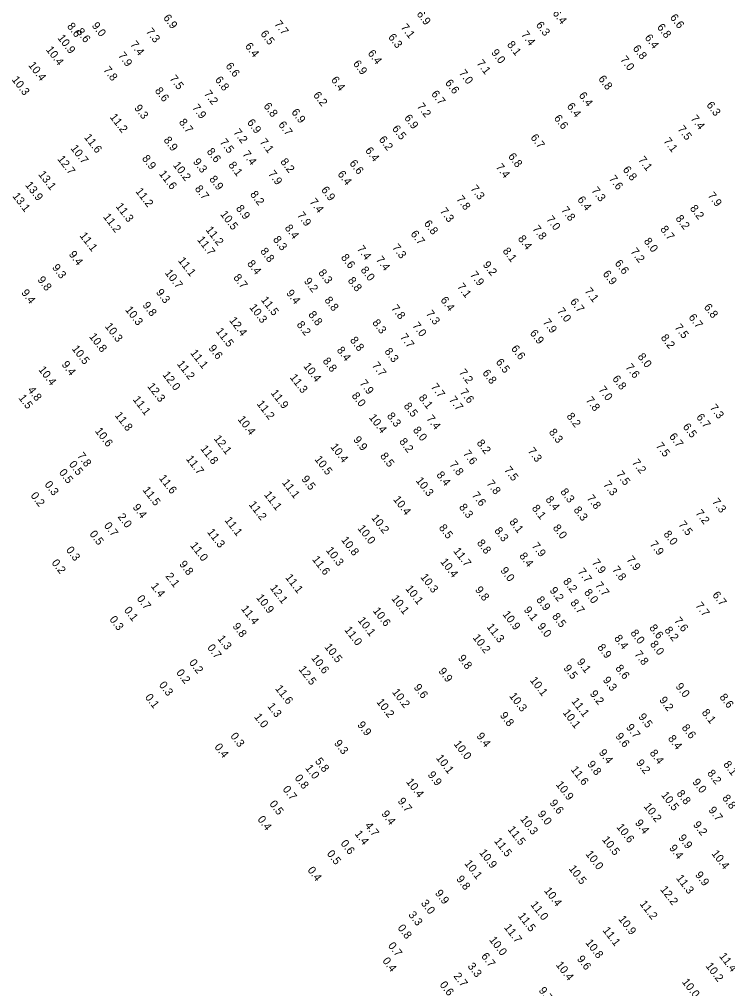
# Model space of a CAD drawing. Extents: x 815385 to 820851, y 582449 to 604245.
# Drawn here: x 818415 to 818858, y 594576 to 595182 of the extents above; entities that cross this region are included whole.
import ezdxf

# ---------------------------------------------------------------- set-up
doc = ezdxf.new("R2010")
doc.units = 0
for name, color, linetype in [('V-TOPO-SOUN-011609', 7, 'Continuous'), ('V-TOPO-SOUN-020509C', 7, 'Continuous'), ('V-TOPO-SOUN-EXCSS', 7, 'Continuous')]:
    doc.layers.add(name, color=color, linetype=linetype)

msp = doc.modelspace()

# ---------------------------------------------------------------- texts
at = {"layer": 'V-TOPO-SOUN-011609'}
for s, p in [('6.9', (818504.66, 595182.61)), ('6.9', (818662.99, 595184.99)), ('6.4', (818747.96, 595185.51)), ('6.6', (818821.32, 595182.82)), ('8.6', (818444.56, 595177.35)), ('7.7', (818574.09, 595178.74)), ('7.1', (818653.09, 595176.68)), ('6.3', (818737.53, 595178.14)), ('6.8', (818813.23, 595176.75)), ('7.3', (818493.86, 595174.04)), ('6.5', (818565.39, 595172.62)), ('6.3', (818645.22, 595170.53)), ('7.4', (818728.28, 595172.12)), ('6.4', (818805.52, 595170.18)), ('7.4', (818483.99, 595165.94)), ('6.4', (818555.75, 595164.88)), ('8.1', (818719.49, 595165.9)), ('6.8', (818798.05, 595163.45)), ('7.9', (818476.46, 595159.02)), ('6.4', (818632.43, 595160.44)), ('9.0', (818709.6, 595160.88)), ('6.6', (818543.62, 595152.52)), ('6.9', (818623.26, 595153.96)), ('7.1', (818700.46, 595154.23)), ('7.0', (818790.22, 595156.52)), ('7.8', (818467.24, 595150.11)), ('7.0', (818689.43, 595148.06)), ('6.8', (818536.98, 595143.9)), ('6.4', (818609.48, 595143.81)), ('6.6', (818680.79, 595141.97)), ('6.8', (818776.52, 595144.48)), ('7.2', (818530.08, 595135.15)), ('6.2', (818598.38, 595134.29)), ('6.7', (818672.1, 595135.07)), ('6.4', (818764.31, 595134.09)), ('7.2', (818663.17, 595127.28)), ('6.4', (818756.88, 595127.34)), ('6.3', (818844.1, 595128.13)), ('7.9', (818522.73, 595126.44)), ('6.9', (818584.74, 595123.65)), ('8.7', (818514.44, 595117.42)), ('6.7', (818576.57, 595115.85)), ('6.9', (818655.24, 595120.06)), ('6.6', (818748.84, 595119.87)), ('7.4', (818834.22, 595119.65)), ('6.5', (818647.68, 595113.35)), ('7.5', (818826.1, 595113.08)), ('8.9', (818504.89, 595106.21)), ('7.1', (818564.88, 595105.04)), ('6.2', (818639.36, 595106.6)), ('6.7', (818734.16, 595107.83)), ('7.1', (818817.25, 595105.58)), ('7.4', (818554.14, 595097.45)), ('6.4', (818630.84, 595099.69)), ('8.1', (818545.39, 595090.61)), ('6.6', (818621.02, 595091.73)), ('6.8', (818720.18, 595096.02)), ('7.1', (818801.43, 595093.89)), ('6.4', (818613.59, 595084.95)), ('7.4', (818712.46, 595089.38)), ('6.8', (818791.82, 595087.78)), ('8.9', (818533.42, 595081.84)), ('7.6', (818783.14, 595082.04)), ('8.7', (818524.38, 595075.83)), ('6.9', (818603.32, 595075.12)), ('7.3', (818696.67, 595075.89)), ('7.3', (818772.28, 595074.7)), ('7.4', (818596.08, 595067.59)), ('7.8', (818687.82, 595069.36)), ('6.4', (818763.4, 595069.03)), ('7.9', (818844.88, 595071.56)), ('7.3', (818677.52, 595061.81)), ('7.8', (818753.31, 595062.51)), ('8.2', (818833.76, 595063.58)), ('7.9', (818588.29, 595059.27)), ('7.0', (818744.01, 595056.73)), ('8.2', (818824.81, 595057.23)), ('8.4', (818580.59, 595051.31)), ('6.8', (818667.56, 595054.05)), ('7.8', (818735.36, 595050.81)), ('8.7', (818815.26, 595050.54)), ('8.3', (818573.24, 595044.13)), ('6.7', (818659.22, 595047.62)), ('8.4', (818726.27, 595044.63)), ('8.0', (818804.97, 595043.03)), ('8.8', (818565.29, 595036.78)), ('7.3', (818647.72, 595039.1)), ('8.1', (818716.73, 595036.93)), ('7.2', (818796.66, 595036.56)), ('7.4', (818637.58, 595031.51)), ('8.4', (818557.09, 595029.07)), ('8.0', (818627.99, 595025.08)), ('9.2', (818704.35, 595028.36)), ('6.6', (818786.8, 595029.28)), ('8.8', (818619.96, 595018.5)), ('7.9', (818696.37, 595022.05)), ('6.9', (818779.29, 595022.65)), ('7.1', (818688.29, 595014.65)), ('7.1', (818767.96, 595011.88)), ('8.8', (818605.41, 595006.24)), ('6.4', (818677.88, 595006.24)), ('7.0', (818750.73, 594999.39)), ('6.7', (818758.93, 595005.28)), ('6.8', (818842.48, 595001.87)), ('8.8', (818595.31, 594997.23)), ('7.3', (818668.78, 594997.77)), ('6.7', (818832.93, 594995.5)), ('8.2', (818588.01, 594990.95)), ('7.0', (818660.31, 594990.27)), ('7.9', (818741.84, 594992.46)), ('7.5', (818824.15, 594989.18)), ('7.7', (818652.62, 594983.16)), ('6.9', (818733.75, 594985.65)), ('8.2', (818815.56, 594982.77)), ('6.6', (818722.06, 594975.95)), ('8.3', (818642.93, 594974.2)), ('8.0', (818801.07, 594970.93)), ('7.7', (818635.12, 594965.42)), ('6.5', (818712.46, 594967.52)), ('7.6', (818793.52, 594964.33)), ('6.8', (818704.11, 594960.74)), ('7.9', (818627.36, 594954.29)), ('6.8', (818785.28, 594957.1)), ('8.0', (818622.38, 594946.52)), ('7.6', (818690.04, 594948.72)), ('7.0', (818776.61, 594950.29)), ('7.7', (818683.22, 594944)), ('7.8', (818768.72, 594943.75)), ('7.3', (818846.18, 594939)), ('8.2', (818756.7, 594933.7)), ('7.4', (818669.16, 594932.23)), ('6.7', (818837.77, 594933.16)), ('8.0', (818660.68, 594925.09)), ('8.3', (818745.63, 594923.79)), ('6.5', (818829.3, 594927.13)), ('8.2', (818652.13, 594917.88)), ('7.5', (818812.46, 594915.21)), ('6.7', (818820.77, 594921.06)), ('7.3', (818732.43, 594911.96)), ('7.2', (818797.58, 594904.77)), ('7.5', (818717.71, 594900.17)), ('7.5', (818787.63, 594897.42)), ('7.8', (818706.67, 594891.7)), ('7.3', (818779.61, 594891.01)), ('7.6', (818697.46, 594884.37)), ('7.8', (818769.33, 594882.48)), ('7.3', (818847.62, 594880.26)), ('8.3', (818689.5, 594876.91)), ('8.3', (818761.09, 594875.19)), ('7.2', (818837.2, 594873.19)), ('8.0', (818748.12, 594863.96)), ('7.5', (818826.61, 594866.08)), ('8.0', (818817.27, 594860.06)), ('7.9', (818734.92, 594852.72)), ('7.9', (818808.66, 594853.72)), ('8.4', (818727.11, 594846.41)), ('7.9', (818794.16, 594844.13)), ('9.0', (818715.35, 594837.32)), ('7.8', (818785.11, 594837.85)), ('7.7', (818774.48, 594828.12)), ('8.0', (818767.66, 594823.62)), ('6.7', (818847.8, 594822.1)), ('8.7', (818759.05, 594817.14)), ('7.7', (818837.18, 594815.41)), ('8.5', (818747.64, 594808.62)), ('7.6', (818823.84, 594805.98)), ('9.0', (818738.47, 594802.46)), ('8.0', (818808.86, 594791.33)), ('7.8', (818799.1, 594785.08)), ('8.6', (818787.2, 594776.28)), ('9.3', (818779.36, 594768.89)), ('9.2', (818771.22, 594760.35)), ('8.6', (818852.24, 594758.24)), ('8.1', (818841.16, 594748.58)), ('8.6', (818828.64, 594739.15)), ('8.4', (818820.04, 594732.35)), ('8.4', (818808.64, 594723.28)), ('9.2', (818800.16, 594717.17)), ('8.8', (818853.96, 594695.17)), ('9.7', (818845.37, 594687.66)), ('9.2', (818835.75, 594678.56))]:
    msp.add_text(s, height=5, rotation=307.782, dxfattribs=at).set_placement(p)
at = {"layer": 'V-TOPO-SOUN-020509C'}
for s, p in [('10.9 ', (818438.62, 595170.04)), ('10.4 ', (818431.36, 595162.72)), ('10.4 ', (818420.33, 595153.02)), ('10.3 ', (818410, 595144.03)), ('11.2 ', (818471.3, 595120.6)), ('11.6 ', (818455.22, 595107.97)), ('10.7 ', (818446.76, 595101.13)), ('12.7 ', (818438.53, 595094.43)), ('13.1 ', (818426.59, 595084.83)), ('11.6 ', (818502.02, 595085.16)), ('13.9 ', (818418.41, 595078.16)), ('11.2 ', (818487.32, 595074.23)), ('13.1 ', (818410.42, 595071.27)), ('11.3 ', (818474.99, 595064.81)), ('11.2 ', (818467.14, 595058.29)), ('11.2 ', (818531.2, 595050.2)), ('11.1 ', (818452.41, 595046.52)), ('11.7 ', (818525.88, 595044.01)), ('9.4', (818445.66, 595034.85)), ('11.1 ', (818513.93, 595030.96)), ('9.3', (818435.21, 595026.59)), ('9.8', (818426.08, 595018.97)), ('10.7 ', (818505.68, 595023.28)), ('9.4', (818415.96, 595010.88)), ('9.3', (818500.13, 595011.12)), ('11.5 ', (818565.74, 595006.41)), ('10.3 ', (818480.88, 595000.26)), ('9.8', (818491.72, 595003.02)), ('10.3 ', (818558.47, 595001.71)), ('10.3 ', (818468.22, 594989.87)), ('12.4 ', (818545.94, 594993.59)), ('10.8 ', (818458.36, 594983.5)), ('11.5 ', (818537.57, 594986.83)), ('10.5 ', (818447.53, 594975.91)), ('9.6', (818532.92, 594976.19)), ('11.1 ', (818521.6, 594973.25)), ('9.4', (818441.16, 594966.02)), ('11.2 ', (818513.26, 594966.38)), ('10.4 ', (818592.26, 594965)), ('10.4 ', (818426.69, 594962.83)), ('12.0 ', (818504.21, 594959.64)), ('11.3 ', (818583.78, 594957.95)), ('12.3 ', (818494.76, 594952.39)), ('4.8', (818419.88, 594950.07)), ('11.9 ', (818571.85, 594948.26)), ('1.5', (818414.23, 594945.18)), ('11.1 ', (818485.66, 594944.18)), ('11.2 ', (818563.11, 594941.47)), ('11.8 ', (818474.39, 594934.29)), ('10.4 ', (818551.2, 594931.8)), ('10.6 ', (818462.01, 594924.47)), ('12.1 ', (818536.28, 594919.76)), ('9.9', (818623.43, 594919.07)), ('7.8', (818450.88, 594908.98)), ('11.8 ', (818527.89, 594913.49)), ('10.4 ', (818609.16, 594914.6)), ('0.5', (818445.73, 594903.72)), ('11.7 ', (818518.89, 594907.08)), ('10.5 ', (818599.22, 594906.85)), ('0.5', (818439.5, 594898.58)), ('0.3', (818430.51, 594891.08)), ('11.6 ', (818501.99, 594895.05)), ('11.1 ', (818578.9, 594892.25)), ('9.5', (818591.02, 594894.47)), ('11.5 ', (818491.8, 594887.65)), ('0.2', (818421.77, 594884.15)), ('11.1 ', (818567.65, 594884.74)), ('10.4 ', (818648.36, 594881.78)), ('9.4', (818485.56, 594876.83)), ('11.2 ', (818558.12, 594878.54)), ('2.0', (818476.22, 594870.88)), ('11.1 ', (818543.01, 594868.76)), ('10.2 ', (818634.69, 594870.26)), ('0.7', (818467.62, 594865.36)), ('11.3 ', (818532.11, 594861.36)), ('10.0 ', (818626.12, 594863.67)), ('0.5', (818458.59, 594860.15)), ('10.8 ', (818615.86, 594856.43)), ('0.3', (818443.9, 594850.17)), ('11.0 ', (818521.5, 594852.97)), ('10.3 ', (818606.32, 594849.97)), ('11.7 ', (818685.94, 594849.5)), ('11.6 ', (818597.74, 594844.28)), ('10.4 ', (818677.83, 594842.8)), ('0.2', (818434.9, 594842.16)), ('9.8', (818514.65, 594841.29)), ('2.1', (818506.08, 594833.77)), ('11.1 ', (818580.94, 594832.99)), ('10.3 ', (818665.37, 594833.21)), ('1.4', (818496.95, 594827.56)), ('12.1 ', (818571.36, 594826.47)), ('10.1 ', (818656.03, 594825.97)), ('0.7', (818488.13, 594819.78)), ('10.9 ', (818562.77, 594820.4)), ('10.1 ', (818647.23, 594819.84)), ('0.1', (818480.12, 594812.57)), ('11.4 ', (818553.31, 594813.41)), ('0.3', (818471.03, 594806.78)), ('10.6 ', (818635.66, 594812.21)), ('10.9 ', (818716.71, 594809.99)), ('9.8', (818547.98, 594802.49)), ('11.0 ', (818617.85, 594800.28)), ('10.1 ', (818626.23, 594806.17)), ('11.3 ', (818706.74, 594802.14)), ('1.3', (818538.6, 594794.71)), ('10.2 ', (818698.03, 594795.44)), ('0.7', (818532.16, 594789.1)), ('10.5 ', (818605.4, 594789.62)), ('10.6 ', (818597.15, 594782.68)), ('9.8', (818688.82, 594782.55)), ('0.2', (818520.78, 594779.79)), ('0.2', (818512.78, 594773.52)), ('12.5 ', (818589.26, 594775.63)), ('9.9', (818676.63, 594774.42)), ('0.3', (818501.99, 594765.86)), ('9.6', (818661.2, 594764.29)), ('10.1 ', (818733.81, 594768.77)), ('0.1', (818493.29, 594758.15)), ('11.6 ', (818574.61, 594763.62)), ('10.2 ', (818647.67, 594761.36)), ('10.3 ', (818720.85, 594758.95)), ('1.3', (818569.76, 594752.52)), ('10.2 ', (818637.9, 594755.21)), ('1.0', (818561.46, 594745.93)), ('9.8', (818715.01, 594746.81)), ('9.9', (818625.93, 594740.92)), ('0.3', (818546.6, 594733.89)), ('9.4', (818700.39, 594733.9)), ('9.3', (818611.44, 594729.4)), ('10.0 ', (818686.14, 594729)), ('0.4', (818536.67, 594727.14)), ('9.4', (818776.84, 594723.55)), ('5.8', (818599.5, 594718.22)), ('10.1 ', (818675.12, 594720.24)), ('9.8', (818769.62, 594716.31)), ('1.0', (818593.39, 594713.94)), ('9.9', (818669.92, 594709.74)), ('11.6 ', (818759.32, 594713)), ('0.8', (818586.77, 594707.73)), ('10.4 ', (818656.41, 594705.33)), ('10.9 ', (818750, 594703.64)), ('0.7', (818579.27, 594700.7)), ('0.5', (818570.99, 594691.53)), ('9.7', (818651.17, 594693.24)), ('9.6', (818746.07, 594692.09)), ('9.4', (818640.99, 594685.28)), ('9.0', (818738.59, 594685.24)), ('10.2 ', (818804.92, 594689.98)), ('0.4', (818563.55, 594681.87)), ('10.3 ', (818727.7, 594682.1)), ('9.4', (818799.5, 594679.64)), ('4.7', (818630.62, 594677.99)), ('11.5 ', (818719.94, 594675.54)), ('10.6 ', (818787.87, 594677.08)), ('0.6', (818615.48, 594666.85)), ('1.4', (818624.31, 594672.81)), ('11.5 ', (818711.42, 594668.35)), ('10.5 ', (818778.86, 594669.23)), ('10.9 ', (818702.11, 594661.11)), ('0.5', (818606.89, 594660.47)), ('10.0 ', (818768.57, 594660.22)), ('0.4', (818594.81, 594650.15)), ('10.1 ', (818692.87, 594654.33)), ('10.5 ', (818758.02, 594651.1)), ('9.8', (818687.77, 594644.6)), ('11.3 ', (818825.17, 594645.14)), ('9.9', (818837.01, 594647.16)), ('10.4 ', (818742.64, 594637.34)), ('12.2 ', (818815.23, 594638.11)), ('9.9', (818674.51, 594635.76)), ('3.0', (818665.66, 594629.52)), ('11.0 ', (818734.16, 594628.63)), ('11.2 ', (818802.39, 594629.09)), ('3.3', (818657.85, 594622.3)), ('11.5 ', (818726.33, 594621.54)), ('10.9 ', (818789.09, 594619.59)), ('0.8', (818651.13, 594614.06)), ('11.7 ', (818717.63, 594614.39)), ('11.1 ', (818779.25, 594612.56)), ('10.0 ', (818708.34, 594606.59)), ('0.7', (818645.11, 594602.95)), ('10.8 ', (818768.49, 594604.85)), ('6.7', (818703.33, 594596.37)), ('9.6', (818763.18, 594594.66)), ('11.4 ', (818852.09, 594596.4)), ('0.4', (818641.62, 594593.49)), ('3.3', (818694.86, 594590.14)), ('10.4 ', (818750.02, 594590.98)), ('10.2 ', (818843.6, 594590.28)), ('2.7', (818686.03, 594584)), ('0.6', (818677.37, 594578.54)), ('10.0 ', (818828.78, 594580.33)), ('9.7', (818739.28, 594574.97))]:
    msp.add_text(s, height=5, rotation=307.782, dxfattribs=at).set_placement(p)
at = {"layer": 'V-TOPO-SOUN-EXCSS'}
for s, p in [('9.0', (818460.01, 595177.72)), ('8.6', (818450.33, 595174)), ('7.5', (818508.63, 595144.64)), ('8.6', (818499.43, 595137.08)), ('6.8', (818567.34, 595127.45)), ('9.3', (818486.56, 595126.23)), ('6.9', (818557.05, 595117.21)), ('7.2', (818548.47, 595111.05)), ('7.5', (818540.02, 595104.9)), ('8.6', (818531.83, 595099.07)), ('8.9', (818491.39, 595094.72)), ('9.3', (818523.28, 595092.64)), ('8.2', (818577.84, 595092.7)), ('10.2 ', (818510.77, 595090.59)), ('7.9', (818570.21, 595085.11)), ('8.2', (818558.96, 595072.33)), ('8.9', (818550.09, 595063.53)), ('10.5 ', (818540.3, 595059.92)), ('7.4', (818625.74, 595038.24)), ('8.6', (818615.7, 595032.88)), ('8.7', (818548.48, 595020.33)), ('9.2', (818592.58, 595018.06)), ('8.3', (818601.57, 595023.36)), ('9.4', (818581.51, 595010.62)), ('7.8', (818647.09, 595001.15)), ('8.3', (818635.3, 594992.13)), ('8.8', (818621.35, 594981.23)), ('8.4', (818613.09, 594975)), ('8.8', (818604.32, 594968.22)), ('7.2', (818689.41, 594961.04)), ('7.7', (818671.84, 594952.07)), ('8.5', (818654.95, 594940.1)), ('8.1', (818664.29, 594945.23)), ('8.3', (818644.44, 594933.9)), ('10.4 ', (818633.2, 594932.93)), ('8.2', (818700.52, 594917.01)), ('7.6', (818691.97, 594910.35)), ('8.5', (818640.2, 594908.87)), ('7.8', (818683.5, 594903.52)), ('8.4', (818675.35, 594897.08)), ('10.3 ', (818662.49, 594893.52)), ('8.3', (818752.83, 594886.51)), ('8.4', (818743.55, 594881.65)), ('8.1', (818735, 594876.22)), ('8.1', (818720.93, 594867.71)), ('8.5', (818676.88, 594864.06)), ('8.3', (818711.57, 594862.25)), ('8.8', (818700.68, 594854.56)), ('7.9', (818772.46, 594842.25)), ('7.7', (818763.64, 594836.57)), ('8.2', (818754.49, 594830.49)), ('9.8', (818699.52, 594825.24)), ('9.2', (818746.11, 594824.85)), ('8.9', (818737.77, 594819.06)), ('9.1', (818729.96, 594812.73)), ('8.6', (818808.38, 594801.5)), ('8.2', (818817.87, 594800.08)), ('8.4', (818786.45, 594794.98)), ('8.0', (818796.64, 594798.29)), ('8.9', (818775.96, 594789.32)), ('9.5', (818754.75, 594776.33)), ('9.1', (818763.1, 594780.23)), ('9.0', (818824.78, 594764.9)), ('11.1 ', (818759.74, 594755.66)), ('9.2', (818814.62, 594756.39)), ('10.1 ', (818754.32, 594748.55)), ('9.5', (818801.57, 594745.94)), ('9.6', (818787.23, 594733.76)), ('9.7', (818793.88, 594739.36)), ('8.1', (818854.68, 594716.2)), ('8.2', (818844.54, 594710.7)), ('9.0', (818835.34, 594705.17)), ('8.8', (818825.47, 594698.01)), ('10.5 ', (818815.81, 594697.1)), ('9.9', (818826.5, 594670.32)), ('9.4', (818820.8, 594663.94)), ('10.4 ', (818847.29, 594660.51))]:
    msp.add_text(s, height=5, rotation=307.782, dxfattribs=at).set_placement(p)

doc.saveas('drawing.dxf')
